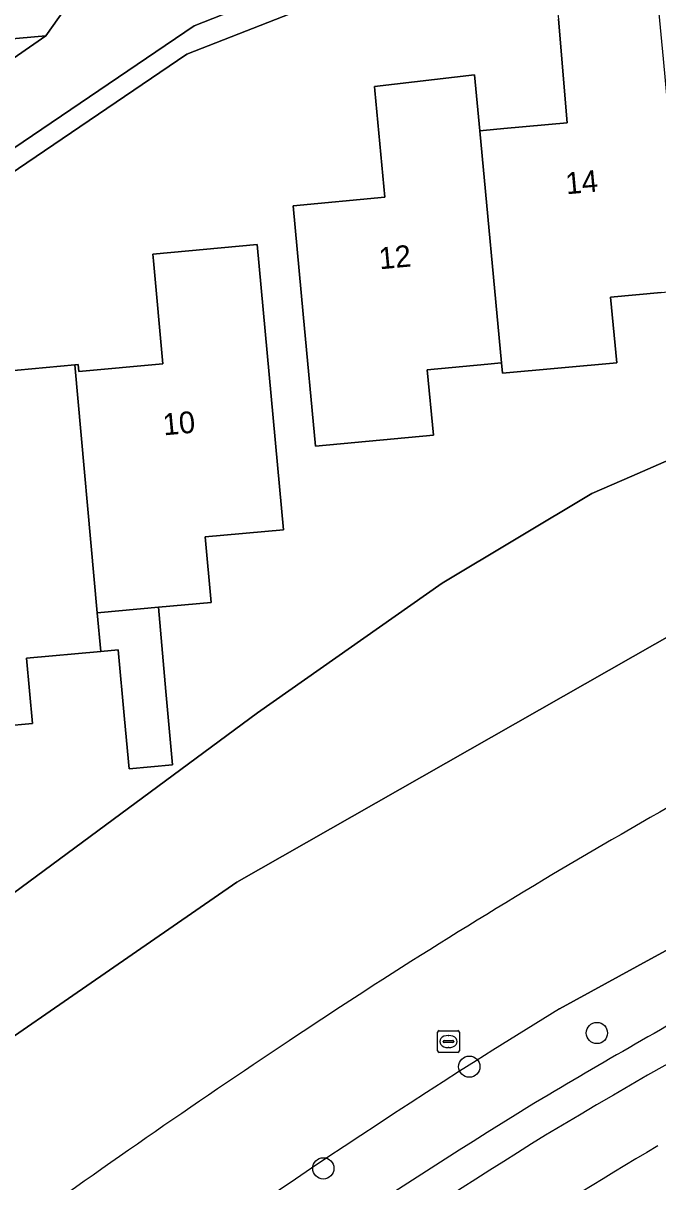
# Model space of a CAD drawing. Extents: x 157793 to 159380, y 380877 to 382313.
# Drawn here: x 158366.2 to 158395.4, y 381110.9 to 381164.2 of the extents above; entities that cross this region are included whole.
import ezdxf

# ---------------------------------------------------------------- set-up
doc = ezdxf.new("R2010")
doc.units = 0
for name, color, linetype in [('IMGEO_Berm_groen', 7, 'Continuous'), ('IMGEO_Boom', 7, 'Continuous'), ('IMGEO_Damwand', 7, 'Continuous'), ('IMGEO_Erf', 7, 'Continuous'), ('IMGEO_Fietspad_gesloten', 7, 'Continuous'), ('IMGEO_Oever', 7, 'Continuous'), ('IMGEO_Pand', 7, 'Continuous'), ('IMGEO_Pand_nummerreeks', 7, 'Continuous'), ('IMGEO_Parkeervlak_open', 7, 'Continuous'), ('IMGEO_Rijbaan_lokaal_open', 7, 'Continuous'), ('IMGEO_Rioolput', 7, 'Continuous'), ('IMGEO_Voetpad_open', 7, 'Continuous'), ('IMGEO_Waterloop', 7, 'Continuous')]:
    doc.layers.add(name, color=color, linetype=linetype)

msp = doc.modelspace()

# ---------------------------------------------------------------- linework, layer by layer
at = {"layer": 'IMGEO_Berm_groen'}
msp.add_lwpolyline([(158421.335, 381134.294), (158416.785, 381132.204), (158403.067, 381125.478), (158395.088, 381121.127), (158390.889, 381118.837)], dxfattribs=at)
for centre, radius, start, end in [((158536.795, 380869.107), 286.072, 118.86107, 120.98864), ((158570.799, 380826.847), 342.967, 121.6393, 126.4698), ((158550.34, 380853.137), 306.755, 121.62179, 126.18157), ((158534.56, 380878.737), 272.072, 120.76093, 124.72052)]:
    msp.add_arc(centre, radius, start, end, dxfattribs=at)
at = {"layer": 'IMGEO_Boom'}
for centre in [(158392.605, 381117.718), (158386.74, 381116.17), (158380.032, 381111.493)]:
    msp.add_circle(centre, 0.489, dxfattribs=at)
at = {"layer": 'IMGEO_Damwand'}
msp.add_lwpolyline([(158439.392, 381154.94), (158431.317, 381152.221), (158402.773, 381139.885), (158376.054, 381124.651), (158357.637, 381111.936), (158348.918, 381105.01)], dxfattribs=at)
for centre, radius, start, end in [((158534.595, 380883.509), 281.183, 117.03356, 123.72874), ((158606.441, 380774.637), 411.623, 123.63138, 128.05708)]:
    msp.add_arc(centre, radius, start, end, dxfattribs=at)
at = {"layer": 'IMGEO_Erf'}
for points in [[(158437.204, 381187.562), (158373.758, 381162.728), (158343.94, 381142.482), (158343.198, 381150.791), (158342.282, 381161.356), (158341.995, 381161.349), (158340.113, 381161.096), (158339.015, 381171.348)], [(158387.219, 381159.214), (158387.382, 381159.229), (158388.329, 381159.316), (158391.245, 381159.584), (158390.835, 381164.352)], [(158395.555, 381151.78), (158393.239, 381151.565), (158393.519, 381148.547), (158388.261, 381148.059), (158388.216, 381148.536), (158388.057, 381148.521), (158387.59, 381148.478), (158384.811, 381148.219), (158385.089, 381145.212), (158379.672, 381144.708), (158379.108, 381150.782), (158378.645, 381155.76), (158382.861, 381156.155), (158382.4, 381161.057), (158382.382, 381161.248), (158386.978, 381161.789), (158387.219, 381159.214)], [(158343.357, 381108.507), (158353.938, 381116.139), (158365.791, 381124.148), (158377, 381132.447), (158385.487, 381138.402), (158392.367, 381142.523), (158394.215, 381143.332), (158402.33, 381146.878), (158411.111, 381150.536), (158415.517, 381152.366), (158420.131, 381154.666), (158424.709, 381156.548), (158431.501, 381158.604), (158437.246, 381160.472)], [(158363.976, 381148.017), (158368.611, 381148.442), (158368.766, 381148.456), (158368.796, 381148.138), (158372.65, 381148.491), (158372.218, 381153.225), (158372.189, 381153.541), (158376.995, 381153.98), (158377.449, 381149.001), (158378.192, 381140.857), (158374.606, 381140.53), (158374.88, 381137.52), (158372.448, 381137.299), (158372.798, 381133.426), (158373.102, 381130.053), (158371.099, 381129.872), (158370.893, 381132.149), (158370.605, 381135.337), (158369.801, 381135.265), (158366.381, 381134.953), (158366.656, 381131.953), (158363.978, 381131.709)]]:
    msp.add_lwpolyline(points, dxfattribs=at)
at = {"layer": 'IMGEO_Fietspad_gesloten'}
for centre, radius, start, end in [((158536.355, 380870.037), 283.526, 115.15573, 121.01923), ((158570.544, 380822.943), 341.541, 121.86327, 125.92636), ((158534.56, 380878.737), 272.072, 120.76093, 124.72052)]:
    msp.add_arc(centre, radius, start, end, dxfattribs=at)
at = {"layer": 'IMGEO_Oever'}
for points in [[(158437.246, 381160.472), (158431.501, 381158.604), (158424.709, 381156.548), (158420.131, 381154.666), (158415.517, 381152.366), (158411.111, 381150.536), (158402.33, 381146.878), (158394.215, 381143.332), (158392.367, 381142.523), (158385.487, 381138.402), (158377, 381132.447), (158365.791, 381124.148), (158353.938, 381116.139), (158343.357, 381108.507)], [(158348.918, 381105.01), (158357.637, 381111.936), (158376.054, 381124.651), (158402.773, 381139.885), (158431.317, 381152.221), (158439.392, 381154.94)], [(158390.889, 381118.837), (158395.088, 381121.127), (158403.067, 381125.478), (158416.785, 381132.204), (158421.335, 381134.294)]]:
    msp.add_lwpolyline(points, dxfattribs=at)
for centre, radius, start, end in [((158534.595, 380883.509), 281.183, 117.03356, 123.72874), ((158570.799, 380826.847), 342.967, 121.6393, 126.4698), ((158606.441, 380774.637), 411.623, 123.63138, 128.05708)]:
    msp.add_arc(centre, radius, start, end, dxfattribs=at)
at = {"layer": 'IMGEO_Pand'}
for points in [[(158395.666, 381162.521), (158395.427, 381165.088), (158390.815, 381164.589), (158390.835, 381164.352), (158391.245, 381159.584), (158388.329, 381159.316), (158387.382, 381159.229), (158387.219, 381159.214), (158388.216, 381148.536), (158388.261, 381148.059), (158393.519, 381148.547), (158393.239, 381151.565), (158395.555, 381151.78), (158396.486, 381151.867), (158396.655, 381151.883)], [(158387.219, 381159.214), (158386.978, 381161.789), (158382.382, 381161.248), (158382.4, 381161.057), (158382.861, 381156.155), (158378.645, 381155.76), (158379.108, 381150.782), (158379.672, 381144.708), (158385.089, 381145.212), (158384.811, 381148.219), (158387.59, 381148.478), (158388.057, 381148.521), (158388.216, 381148.536)], [(158368.611, 381148.442), (158369.64, 381137.043), (158369.795, 381137.057), (158370.624, 381137.133), (158372.448, 381137.299), (158374.88, 381137.52), (158374.606, 381140.53), (158378.192, 381140.857), (158377.449, 381149.001), (158376.995, 381153.98), (158372.189, 381153.541), (158372.218, 381153.225), (158372.65, 381148.491), (158368.796, 381148.138), (158368.766, 381148.456)], [(158368.611, 381148.442), (158363.976, 381148.017), (158364.005, 381147.702), (158364.44, 381142.938), (158361.392, 381142.659), (158360.586, 381142.585), (158360.426, 381142.57), (158361.605, 381129.71), (158361.742, 381128.217), (158364.275, 381128.448), (158363.978, 381131.709), (158366.656, 381131.953), (158366.381, 381134.953), (158369.801, 381135.265), (158369.64, 381137.043)], [(158372.448, 381137.299), (158370.624, 381137.133), (158369.795, 381137.057), (158369.64, 381137.043), (158369.801, 381135.265), (158370.605, 381135.337), (158370.893, 381132.149), (158371.099, 381129.872), (158373.102, 381130.053), (158372.798, 381133.426)]]:
    msp.add_lwpolyline(points, close=True, dxfattribs=at)
at = {"layer": 'IMGEO_Parkeervlak_open'}
msp.add_lwpolyline([(158358.835, 381159.932), (158358.743, 381160.903), (158364.098, 381161.387), (158367.267, 381163.571), (158344.097, 381161.52), (158344.919, 381151.126), (158349.465, 381151.46), (158351.299, 381152.697), (158351.054, 381155.379), (158355.938, 381155.83), (158359.022, 381157.939)], close=True, dxfattribs=at)
at = {"layer": 'IMGEO_Rijbaan_lokaal_open'}
for points in [[(158370.425, 381169.72), (158367.973, 381169.48), (158343.608, 381167.271), (158341.415, 381167.069), (158341.995, 381161.349), (158342.282, 381161.356), (158344.097, 381161.52), (158367.267, 381163.571), (158372.156, 381170.485)], [(158372.156, 381170.485), (158367.267, 381163.571), (158364.098, 381161.387), (158359.022, 381157.939), (158355.938, 381155.83), (158351.299, 381152.697), (158349.465, 381151.46), (158345.336, 381148.653), (158345.684, 381144.763), (158374.1, 381164.032), (158380.022, 381166.386)]]:
    msp.add_lwpolyline(points, dxfattribs=at)
at = {"layer": 'IMGEO_Rioolput'}
for p, q in [((158385.283, 381116.9), (158385.283, 381117.752)), ((158385.358, 381117.826), (158386.21, 381117.826)), ((158385.771, 381117.606), (158385.796, 381117.606)), ((158386.284, 381117.752), (158386.284, 381116.9)), ((158385.542, 381117.32), (158385.542, 381117.332)), ((158385.98, 381117.283), (158385.582, 381117.283)), ((158385.585, 381117.369), (158385.983, 381117.369)), ((158385.794, 381117.046), (158385.769, 381117.046)), ((158386.026, 381117.332), (158386.026, 381117.32)), ((158386.21, 381116.826), (158385.358, 381116.826))]:
    msp.add_line(p, q, dxfattribs=at)
for points in [[(158385.283, 381116.9), (158385.283, 381117.752)], [(158385.358, 381117.826), (158386.21, 381117.826)], [(158386.284, 381117.752), (158386.284, 381116.9)], [(158386.21, 381116.826), (158385.358, 381116.826)]]:
    msp.add_lwpolyline(points, dxfattribs=at)
for centre, radius, start, end in [((158385.36, 381117.75), 0.0765, 91.552, 178.448), ((158385.36, 381117.75), 0.0765, 91.552, 178.448), ((158386.208, 381117.75), 0.0765, 1.552, 88.448), ((158386.208, 381117.75), 0.0765, 1.552, 88.448), ((158385.582, 381117.329), 0.0403, 85.8775, 175.7526), ((158385.579, 381117.319), 0.0366, 178.938, 274.7102), ((158385.983, 381117.326), 0.043, 264.8664, 352.4533), ((158385.987, 381117.331), 0.0386, 1.7309, 96.639), ((158385.36, 381116.902), 0.0765, 181.552, 268.448), ((158385.36, 381116.902), 0.0765, 181.552, 268.448), ((158386.208, 381116.902), 0.0765, 271.552, 358.448), ((158386.208, 381116.902), 0.0765, 271.552, 358.448)]:
    msp.add_arc(centre, radius, start, end, dxfattribs=at)
for centre, major_axis, ratio, start_param, end_param in [((158385.77, 381117.326), (-0.387, 0.002), 0.722429, 4.712389, 7.853982), ((158385.795, 381117.326), (-0.39, 0.002), 0.717154, 1.570796, 4.712389)]:
    msp.add_ellipse(centre, major_axis=major_axis, ratio=ratio, start_param=start_param, end_param=end_param, dxfattribs=at)
at = {"layer": 'IMGEO_Voetpad_open'}
msp.add_lwpolyline([(158435.998, 381188.28), (158428.505, 381185.406), (158425.292, 381184.147), (158382.725, 381167.434), (158380.022, 381166.386), (158374.1, 381164.032), (158345.684, 381144.763), (158345.336, 381148.653), (158349.465, 381151.46), (158344.919, 381151.126), (158343.198, 381150.791), (158343.94, 381142.482), (158373.758, 381162.728), (158437.204, 381187.562), (158441.151, 381194.476), (158445.198, 381194.878), (158445.123, 381195.558), (158461.541, 381197.122), (158467.081, 381197.838), (158471.171, 381198.233), (158472.258, 381198.299), (158472.526, 381194.816), (158473.576, 381194.917), (158473.341, 381197.829)], dxfattribs=at)
for centre, radius, start, end in [((158536.355, 380870.037), 283.526, 115.15573, 121.01923), ((158536.795, 380869.107), 286.072, 118.86107, 120.98864), ((158550.34, 380853.137), 306.755, 121.62179, 126.18157), ((158570.544, 380822.943), 341.541, 121.86327, 125.92636)]:
    msp.add_arc(centre, radius, start, end, dxfattribs=at)
at = {"layer": 'IMGEO_Waterloop'}
msp.add_lwpolyline([(158439.392, 381154.94), (158431.317, 381152.221), (158402.773, 381139.885), (158376.054, 381124.651), (158357.637, 381111.936), (158348.918, 381105.01)], dxfattribs=at)
for centre, radius, start, end in [((158534.595, 380883.509), 281.183, 117.03356, 123.72874), ((158606.441, 380774.637), 411.623, 123.63138, 128.05708)]:
    msp.add_arc(centre, radius, start, end, dxfattribs=at)

# ---------------------------------------------------------------- texts
at = {"layer": 'IMGEO_Pand_nummerreeks'}
for s, rotation, p in [('14', 5.2483, (158391.208, 381156.287)), ('12', 5.3514, (158382.625, 381152.838)), ('10', 5.2311, (158372.695, 381145.201))]:
    msp.add_text(s, height=1, rotation=rotation, dxfattribs=at).set_placement(p)

doc.saveas('drawing.dxf')
